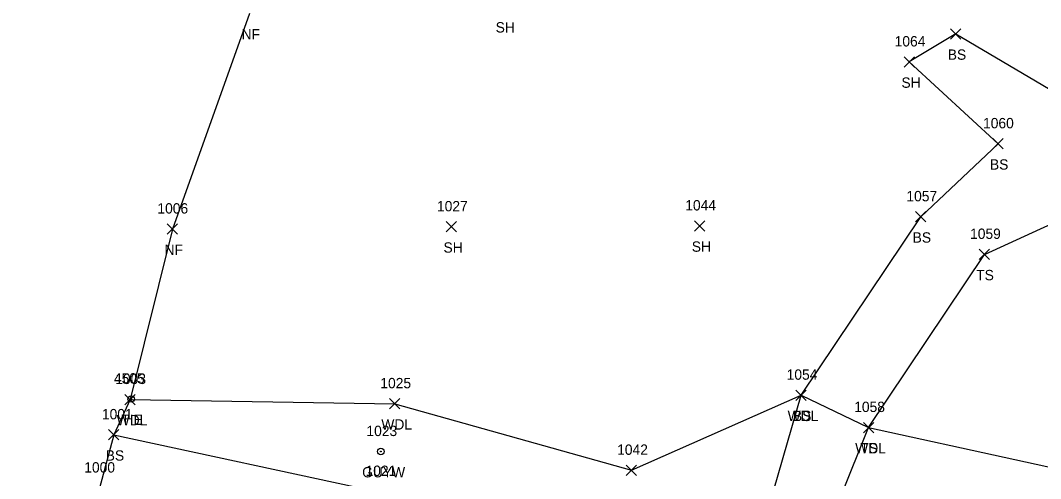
# Model space of a CAD drawing. Extents: x 1509053 to 1511576, y 400838 to 402572.
# Drawn here: x 1509055.4 to 1509252.8, y 402167.8 to 402256.5 of the extents above; entities that cross this region are included whole.
import ezdxf

# ---------------------------------------------------------------- set-up
doc = ezdxf.new("R2010")
doc.units = 0
for name, color, linetype in [('C_A', 7, 'Continuous'), ('C_I', 7, 'Continuous'), ('CBP', 7, 'Continuous'), ('L_A', 7, 'Continuous'), ('L_I', 7, 'Continuous'), ('L_TIC', 7, 'Continuous'), ('LAWA', 7, 'Continuous'), ('LELB', 7, 'Continuous'), ('LSOGP', 7, 'Continuous'), ('U_A', 7, 'Continuous'), ('U_I', 7, 'Continuous'), ('UPGW', 7, 'Continuous')]:
    doc.layers.add(name, color=color, linetype=linetype)

msp = doc.modelspace()

# ---------------------------------------------------------------- linework, layer by layer
at = {"layer": 'CBP'}
for radius in [0.625, 0.0833]:
    msp.add_circle((1509076.8, 402183.25), radius, dxfattribs=at)
at = {"layer": 'L_TIC'}
for points in [[(1509235.36, 402252.91), (1509237.36, 402254.91)], [(1509237.36, 402252.91), (1509235.36, 402254.91)], [(1509226.35, 402247.49), (1509228.35, 402249.49)], [(1509228.35, 402247.49), (1509226.35, 402249.49)], [(1509243.53, 402231.65), (1509245.53, 402233.65)], [(1509245.53, 402231.65), (1509243.53, 402233.65)], [(1509228.57, 402217.52), (1509230.57, 402219.52)], [(1509230.57, 402217.52), (1509228.57, 402219.52)], [(1509083.77, 402215.15), (1509085.77, 402217.15)], [(1509085.77, 402215.15), (1509083.77, 402217.15)], [(1509137.74, 402215.58), (1509139.74, 402217.58)], [(1509139.74, 402215.58), (1509137.74, 402217.58)], [(1509185.79, 402215.75), (1509187.79, 402217.75)], [(1509187.79, 402215.75), (1509185.79, 402217.75)], [(1509240.9, 402210.24), (1509242.9, 402212.24)], [(1509242.9, 402210.24), (1509240.9, 402212.24)], [(1509075.57, 402182.15), (1509077.57, 402184.15)], [(1509077.57, 402182.15), (1509075.57, 402184.15)], [(1509205.41, 402182.98), (1509207.4, 402184.98)], [(1509207.4, 402182.98), (1509205.41, 402184.98)], [(1509205.41, 402182.98), (1509207.4, 402184.98)], [(1509207.4, 402182.98), (1509205.41, 402184.98)], [(1509126.79, 402181.33), (1509128.79, 402183.33)], [(1509128.79, 402181.33), (1509126.79, 402183.33)], [(1509218.47, 402176.73), (1509220.47, 402178.73)], [(1509220.47, 402176.73), (1509218.47, 402178.73)], [(1509218.47, 402176.73), (1509220.47, 402178.73)], [(1509220.47, 402176.73), (1509218.47, 402178.73)], [(1509072.43, 402175.32), (1509074.43, 402177.32)], [(1509074.43, 402175.32), (1509072.43, 402177.32)], [(1509172.6, 402168.45), (1509174.6, 402170.45)], [(1509174.6, 402168.45), (1509172.6, 402170.45)]]:
    msp.add_lwpolyline(points, dxfattribs=at)
at = {"layer": 'LAWA'}
msp.add_lwpolyline([(1509076.57, 402183.15), (1509127.79, 402182.33), (1509173.6, 402169.45), (1509206.41, 402183.98), (1509219.47, 402177.73), (1509276.12, 402165.35), (1509324.31, 402150.34), (1509333.92, 402141.66), (1509378.2, 402140.76), (1509422.99, 402135.87), (1509484.22, 402126.37), (1509536.38, 402111.03), (1509587.67, 402075.95), (1509623.1, 402040.21), (1509661.3, 402001.82), (1509687.76, 401950.54), (1509742.09, 401890.27)], dxfattribs=at)
at = {"layer": 'LELB'}
for points in [[(1509236.36, 402253.91), (1509227.35, 402248.49)], [(1509236.36, 402253.91), (1509255.73, 402242.53)], [(1509244.53, 402232.65), (1509227.35, 402248.49)], [(1509073.43, 402176.32), (1509124.36, 402165.36), (1509168.15, 402150.53), (1509197.52, 402153.15), (1509206.41, 402183.98), (1509229.57, 402218.52), (1509244.53, 402232.65)], [(1509208.66, 402150.69), (1509219.47, 402177.73), (1509241.9, 402211.24), (1509264.28, 402221.5)]]:
    msp.add_lwpolyline(points, dxfattribs=at)
at = {"layer": 'LSOGP'}
msp.add_lwpolyline([(1509099.68, 402257.85), (1509084.77, 402216.15), (1509076.57, 402183.15), (1509073.43, 402176.32), (1509070.66, 402166.02), (1509069.74, 402162.61), (1509066.35, 402150.83), (1509063.17, 402139.1), (1509061.77, 402134.39), (1509061.54, 402133.56), (1509058.33, 402126.15), (1509055.36, 402108.79), (1509088.64, 402089.81), (1509104.93, 402090.55), (1509139.24, 402082.08), (1509152.55, 402075.44), (1509177.52, 402071.59), (1509197.64, 402060.42), (1509219.32, 402052.84), (1509231.98, 402043.7), (1509281.69, 402042.53)], dxfattribs=at)
at = {"layer": 'UPGW'}
for radius in [0.625, 0.0833]:
    msp.add_circle((1509125.1, 402173.08), radius, dxfattribs=at)

# ---------------------------------------------------------------- texts
at = {"layer": 'C_A'}
msp.add_text('TIE', height=2, dxfattribs=at).set_placement((1509074.88, 402178.25))
at = {"layer": 'C_I'}
msp.add_text('4505', height=2, dxfattribs=at).set_placement((1509073.46, 402186.25))
at = {"layer": 'L_A'}
for s, p in [('NF', (1509098.16, 402252.85)), ('SH', (1509147.32, 402254.19)), ('BS', (1509234.8, 402248.91)), ('SH', (1509225.84, 402243.49)), ('BS', (1509242.97, 402227.65)), ('BS', (1509228.01, 402213.52)), ('NF', (1509083.25, 402211.15)), ('SH', (1509137.23, 402211.58)), ('SH', (1509185.27, 402211.75)), ('TS', (1509240.31, 402206.24)), ('WDL', (1509073.99, 402178.15)), ('WDL', (1509203.82, 402178.98)), ('BS', (1509204.85, 402178.98)), ('WDL', (1509125.2, 402177.33)), ('WDL', (1509216.89, 402172.73)), ('TS', (1509217.88, 402172.73)), ('BS', (1509071.87, 402171.32))]:
    msp.add_text(s, height=2, dxfattribs=at).set_placement(p)
at = {"layer": 'L_I'}
for s, p in [('1064', (1509224.53, 402251.49)), ('1060', (1509241.63, 402235.65)), ('1057', (1509226.8, 402221.52)), ('1006', (1509081.87, 402219.15)), ('1027', (1509135.97, 402219.58)), ('1044', (1509184.01, 402219.75)), ('1059', (1509239.12, 402214.24)), ('1003', (1509073.72, 402186.15)), ('1054', (1509203.63, 402186.98)), ('1054', (1509203.63, 402186.98)), ('1025', (1509125.01, 402185.33)), ('1058', (1509216.7, 402180.73)), ('1058', (1509216.7, 402180.73)), ('1001', (1509071.14, 402179.32)), ('1042', (1509170.83, 402172.45)), ('1000', (1509067.72, 402169.02)), ('1021', (1509122.15, 402168.36))]:
    msp.add_text(s, height=2, dxfattribs=at).set_placement(p)
at = {"layer": 'U_A'}
msp.add_text('GUYW', height=2, dxfattribs=at).set_placement((1509121.49, 402168.08))
at = {"layer": 'U_I'}
msp.add_text('1023', height=2, dxfattribs=at).set_placement((1509122.32, 402176.08))

doc.saveas('drawing.dxf')
